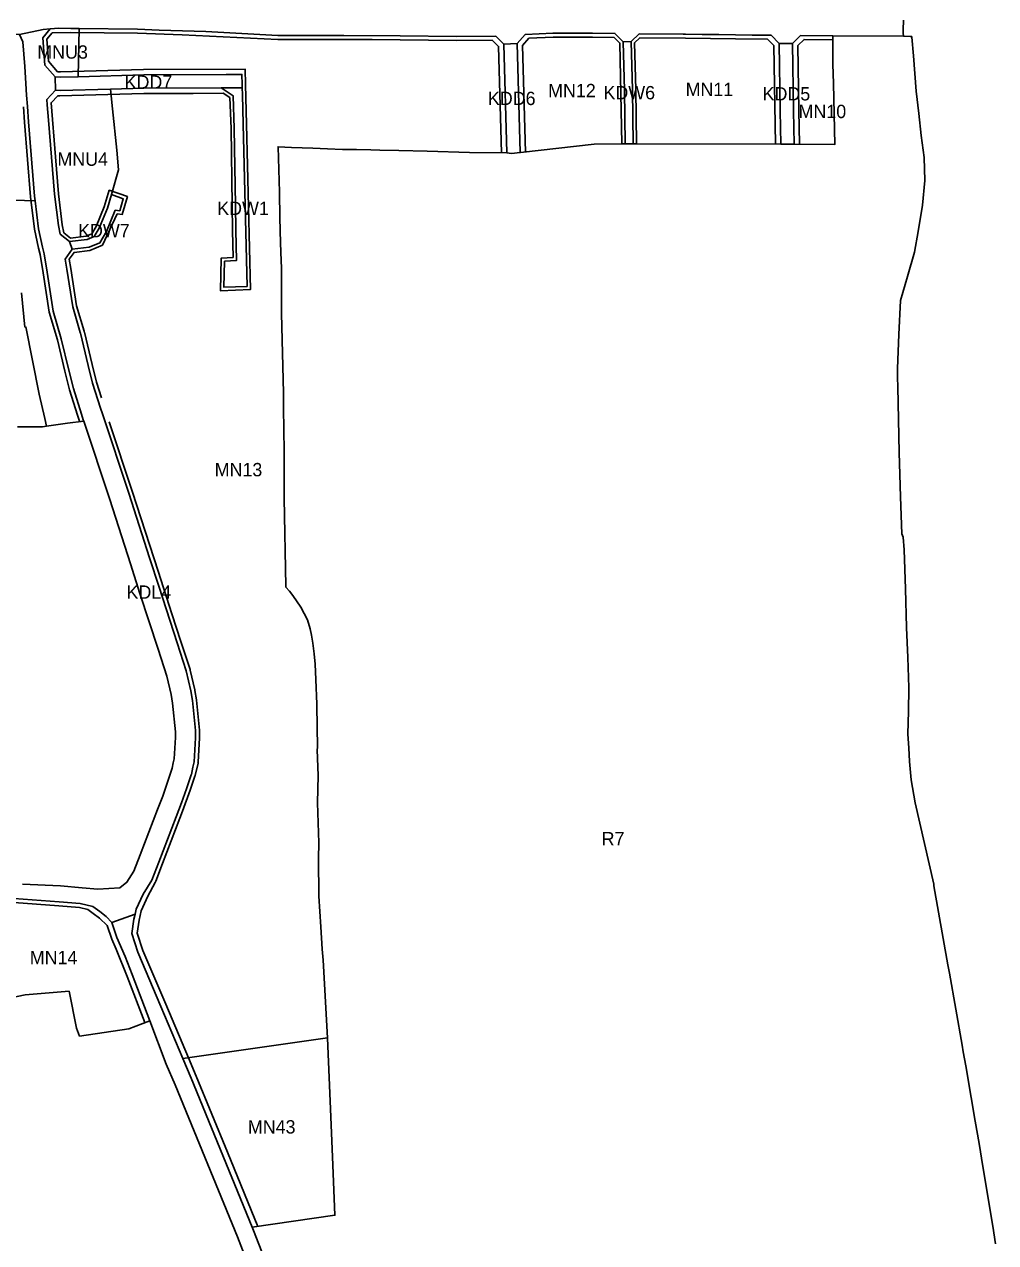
# Model space of a CAD drawing. Extents: x 7440055 to 7442242, y 5549003 to 5552256.
# Drawn here: x 7441503 to 7442231, y 5550566 to 5551479 of the extents above; entities that cross this region are included whole.
import ezdxf

# ---------------------------------------------------------------- set-up
doc = ezdxf.new("R2010")
doc.units = 0
for name, color, linetype in [('linie_rozgraniczajace', 7, 'Continuous'), ('linie_zabudowy_nieprzekraczalne', 7, 'Continuous'), ('oznaczenia_przeznaczen', 7, 'Continuous')]:
    doc.layers.add(name, color=color, linetype=linetype)

msp = doc.modelspace()

# ---------------------------------------------------------------- linework, layer by layer
at = {"layer": 'linie_rozgraniczajace'}
for points in [[(7441693.25, 5551470.85), (7441639.3, 5551473.7), (7441604.38, 5551474.86), (7441588.23, 5551475.46), (7441544.55, 5551475.94), (7441538.35, 5551476.01), (7441529.3, 5551476.2), (7441522.84, 5551475.74), (7441517.61, 5551475.36), (7441499.81, 5551471.5)], [(7441499.81, 5551471.5), (7441517.61, 5551475.36), (7441522.84, 5551475.74), (7441517.28, 5551469.14), (7441518.71, 5551448.66), (7441526.46, 5551439.82), (7441526.82, 5551429.77), (7441520.27, 5551422.86), (7441520.62, 5551418.73), (7441521.52, 5551407.33), (7441526, 5551351.81), (7441528.88, 5551328.46), (7441530.21, 5551322.02), (7441537.3, 5551316.36), (7441539.22, 5551310.56), (7441534.07, 5551303.06), (7441535.21, 5551295.75), (7441539.62, 5551267.5), (7441545.32, 5551248.19), (7441545.45, 5551247.82)], [(7441534.07, 5551303.06), (7441539.22, 5551310.56), (7441551.9, 5551312.17), (7441560.01, 5551315.49), (7441564.89, 5551323.79), (7441571.57, 5551339.78), (7441574.89, 5551339.45), (7441577.56, 5551348.48), (7441568.65, 5551351.57), (7441574.05, 5551370.21), (7441572.58, 5551384.86), (7441569.45, 5551415.93), (7441567.98, 5551430.58), (7441592.96, 5551431.25), (7441650.76, 5551431.56), (7441659.81, 5551425.63), (7441660.71, 5551401.1), (7441661.13, 5551372.41), (7441661.54, 5551343.71), (7441661.9, 5551324.82), (7441662.32, 5551302.13), (7441653.35, 5551301.58), (7441652.87, 5551282.1), (7441670.23, 5551282.8), (7441667.42, 5551404.41), (7441666.79, 5551426.65), (7441666.65, 5551431.65), (7441666.58, 5551434.03), (7441666.34, 5551441.65), (7441654.71, 5551441.59), (7441592.8, 5551441.25), (7441543.81, 5551439.93), (7441544.55, 5551475.94), (7441588.23, 5551475.46), (7441604.38, 5551474.86), (7441639.3, 5551473.7), (7441693.25, 5551470.85), (7441742.78, 5551470.89), (7441785.02, 5551470.51), (7441827.26, 5551470.12), (7441856.51, 5551470.3), (7441862.59, 5551464.42), (7441864.83, 5551382.91), (7441836.8, 5551383.23), (7441805.25, 5551384.05), (7441784.06, 5551384.63), (7441769.64, 5551384.95), (7441762.88, 5551385.07), (7441752.28, 5551385.26), (7441741.69, 5551385.44), (7441730.55, 5551385.89), (7441719.41, 5551386.33), (7441703.43, 5551386.97), (7441693.43, 5551387.37), (7441694.46, 5551353.42), (7441694.77, 5551334.17), (7441695.36, 5551315.46), (7441695.79, 5551301.84), (7441695.95, 5551296.75), (7441696.11, 5551262.51), (7441696.89, 5551232.75), (7441697.66, 5551202.99), (7441697.57, 5551192.59), (7441697.82, 5551174.47), (7441698.01, 5551160.09), (7441698.03, 5551124.12), (7441699.32, 5551057.97), (7441699.39, 5551057.36), (7441701.93, 5551054.22), (7441704.48, 5551051.08), (7441710.5, 5551042.42), (7441715.49, 5551032.76), (7441717.49, 5551026.12), (7441718.43, 5551021.35), (7441719.64, 5551015.27), (7441720.51, 5551007.47), (7441721.38, 5550999.68), (7441721.55, 5550993.9), (7441721.71, 5550988.12), (7441722.43, 5550969.68), (7441722.47, 5550968.55), (7441722.68, 5550952.91), (7441722.9, 5550937.27), (7441722.64, 5550935.46), (7441723.39, 5550916.2), (7441722.91, 5550895.73), (7441723.91, 5550865.75), (7441723.79, 5550853.91), (7441724.13, 5550825.71), (7441725.56, 5550802.81), (7441726.41, 5550786.1), (7441727.28, 5550777.68), (7441730.56, 5550719.57), (7441622.21, 5550704.09), (7441605.6, 5550743.12), (7441588.43, 5550783.71), (7441583.94, 5550797.64), (7441585.54, 5550808.42), (7441586.36, 5550812.21), (7441587.17, 5550816)], [(7442161.87, 5551482.19), (7442161.78, 5551475), (7442161.83, 5551472.6), (7442161.89, 5551470.19), (7442108.98, 5551470.62), (7442084.85, 5551470.85), (7442078.87, 5551464.91), (7442068.87, 5551464.87), (7442062.85, 5551470.95), (7442048.64, 5551471.13), (7442023.64, 5551471.44), (7442011.14, 5551471.6), (7441998.64, 5551471.75), (7441996.94, 5551471.77), (7441964.04, 5551472.18), (7441958.01, 5551466.29), (7441952.03, 5551466.19), (7441945.74, 5551472.41), (7441929.05, 5551472.61), (7441899.38, 5551472.48), (7441878.87, 5551471.68), (7441878.6, 5551471.65), (7441872.58, 5551464.86), (7441862.59, 5551464.42), (7441856.51, 5551470.3), (7441827.26, 5551470.12), (7441785.02, 5551470.51), (7441742.78, 5551470.89), (7441693.25, 5551470.85)], [(7441501.97, 5550834.71), (7441530.39, 5550833.54), (7441546.72, 5550832.06), (7441558.57, 5550831.01), (7441574.99, 5550831.99), (7441580.21, 5550836.2), (7441585.46, 5550844.47), (7441590.06, 5550856.66), (7441603.14, 5550890.64), (7441607.04, 5550900.78), (7441614.18, 5550921.62), (7441615.01, 5550925.7), (7441615.76, 5550928.67), (7441616.72, 5550944.58), (7441616.58, 5550948.85), (7441614.43, 5550970.45), (7441613.47, 5550976.83), (7441610.26, 5550990.64), (7441603.61, 5551010.92), (7441590.03, 5551052.68), (7441582.88, 5551074.83), (7441567.41, 5551123.04), (7441547.86, 5551181.86), (7441547.59, 5551182.67), (7441546.2, 5551187.08), (7441540.15, 5551206.18), (7441536.68, 5551220.02), (7441531.04, 5551243.58), (7441524.95, 5551264.21), (7441520.39, 5551293.43), (7441518.24, 5551307.26), (7441516.93, 5551312.11), (7441514.07, 5551326.03), (7441511.48, 5551346.99), (7441511.08, 5551350.28), (7441506.57, 5551406.14), (7441505.67, 5551417.51), (7441504.95, 5551426.05), (7441504.59, 5551434.9), (7441503.74, 5551447.63), (7441502.36, 5551466.11)], [(7441691.57, 5550533), (7441675.15, 5550575.24), (7441674.17, 5550577.63), (7441736.11, 5550586.61), (7441734.26, 5550630.28), (7441732.48, 5550672.04), (7441730.58, 5550719.25), (7441730.56, 5550719.57), (7441727.28, 5550777.68), (7441726.41, 5550786.1), (7441725.56, 5550802.81), (7441724.13, 5550825.71), (7441723.79, 5550853.91), (7441723.91, 5550865.75), (7441722.91, 5550895.73), (7441723.39, 5550916.2), (7441722.64, 5550935.46), (7441722.9, 5550937.27), (7441722.68, 5550952.91), (7441722.47, 5550968.55), (7441722.43, 5550969.68), (7441721.71, 5550988.12), (7441721.55, 5550993.9), (7441721.38, 5550999.68), (7441720.51, 5551007.47), (7441719.64, 5551015.27), (7441718.43, 5551021.35), (7441717.49, 5551026.12), (7441715.49, 5551032.76), (7441710.5, 5551042.42), (7441704.48, 5551051.08), (7441701.93, 5551054.22), (7441699.39, 5551057.36), (7441699.32, 5551057.97), (7441698.03, 5551124.12), (7441698.01, 5551160.09), (7441697.82, 5551174.47), (7441697.57, 5551192.59), (7441697.66, 5551202.99), (7441696.89, 5551232.75), (7441696.11, 5551262.51), (7441695.95, 5551296.75), (7441695.79, 5551301.84), (7441695.36, 5551315.46), (7441694.77, 5551334.17), (7441694.46, 5551353.42), (7441693.43, 5551387.37), (7441703.43, 5551386.97), (7441719.41, 5551386.33), (7441730.55, 5551385.89), (7441741.69, 5551385.44), (7441752.28, 5551385.26), (7441762.88, 5551385.07), (7441769.64, 5551384.95), (7441784.06, 5551384.63), (7441805.25, 5551384.05), (7441836.8, 5551383.23), (7441864.83, 5551382.91), (7441868.35, 5551382.42), (7441874.83, 5551383.13), (7441875.05, 5551383.16), (7441930.22, 5551389.27), (7441951.35, 5551389.61), (7441953.38, 5551389.64), (7441954.39, 5551389.66), (7441958.42, 5551389.72), (7441959.36, 5551389.72), (7441961.34, 5551389.73), (7442070.09, 5551389.35), (7442080.09, 5551389.34), (7442110.64, 5551389.24), (7442109.43, 5551434.74), (7442109.16, 5551449.29), (7442108.98, 5551470.62), (7442161.89, 5551470.19), (7442167.01, 5551470.05), (7442168.21, 5551470.02), (7442168.12, 5551469.49), (7442169.51, 5551455.64), (7442171.49, 5551429.02), (7442173.4, 5551412.46), (7442175.3, 5551395.9), (7442177.42, 5551379.39), (7442178.05, 5551362.03), (7442176.32, 5551343.77), (7442172.94, 5551323.86), (7442170.33, 5551308.42), (7442164.97, 5551290.28), (7442159.61, 5551272.14), (7442158.5, 5551246.73), (7442157.4, 5551221.33), (7442157.53, 5551214.43)], [(7441503.41, 5551347.09), (7441511.48, 5551346.99), (7441514.07, 5551326.03), (7441516.93, 5551312.11), (7441518.24, 5551307.26), (7441520.39, 5551293.43), (7441524.95, 5551264.21), (7441531.04, 5551243.58), (7441536.68, 5551220.02), (7441540.15, 5551206.18), (7441546.2, 5551187.08), (7441547.59, 5551182.67), (7441547.86, 5551181.86), (7441535.8, 5551180.17), (7441519.97, 5551177.95), (7441518.65, 5551183.66), (7441514.44, 5551201.95), (7441509.51, 5551227.17), (7441504.57, 5551252.38), (7441503.83, 5551252.33), (7441501.34, 5551277.98)], [(7441587.17, 5550816), (7441592.32, 5550827.29), (7441598.95, 5550837.73), (7441604.07, 5550851.32), (7441617.14, 5550885.25), (7441621.14, 5550895.65), (7441624.76, 5550906.22), (7441628.38, 5550916.79), (7441628.55, 5550917.03), (7441629.63, 5550922.36), (7441630.65, 5550926.35), (7441631.74, 5550944.38), (7441631.55, 5550949.85), (7441629.32, 5550972.3), (7441628.22, 5550979.64), (7441624.72, 5550994.68), (7441617.86, 5551015.58), (7441604.3, 5551057.3), (7441597.16, 5551079.43), (7441581.67, 5551127.69), (7441561.86, 5551187.3), (7441560.49, 5551191.61), (7441554.59, 5551210.27), (7441551.25, 5551223.59), (7441545.45, 5551247.82), (7441545.32, 5551248.19), (7441539.62, 5551267.5), (7441535.21, 5551295.75), (7441534.07, 5551303.06)], [(7441501.34, 5551277.98), (7441503.83, 5551252.33), (7441504.57, 5551252.38), (7441509.51, 5551227.17), (7441514.44, 5551201.95), (7441518.65, 5551183.66), (7441519.97, 5551177.95), (7441517.12, 5551177.56), (7441498.21, 5551177.47)], [(7441545.45, 5551247.82), (7441551.25, 5551223.59), (7441554.59, 5551210.27), (7441560.49, 5551191.61), (7441561.86, 5551187.3), (7441581.67, 5551127.69), (7441597.16, 5551079.43), (7441604.3, 5551057.3), (7441617.86, 5551015.58), (7441624.72, 5550994.68), (7441628.22, 5550979.64), (7441629.32, 5550972.3), (7441631.55, 5550949.85), (7441631.74, 5550944.38), (7441630.65, 5550926.35), (7441629.63, 5550922.36), (7441628.55, 5550917.03), (7441628.38, 5550916.79), (7441624.76, 5550906.22), (7441621.14, 5550895.65), (7441617.14, 5550885.25), (7441604.07, 5550851.32), (7441598.95, 5550837.73), (7441592.32, 5550827.29), (7441587.17, 5550816), (7441586.36, 5550812.21), (7441569.04, 5550806.07), (7441564.63, 5550810.61), (7441559.99, 5550814.21), (7441554.71, 5550817.95), (7441545.23, 5550820.15), (7441529.41, 5550821.58), (7441495.87, 5550823.99)], [(7442157.53, 5551214.43), (7442157.67, 5551207.53), (7442158.15, 5551182.9), (7442158.63, 5551158.28), (7442159.17, 5551141.7), (7442159.71, 5551125.12), (7442160.63, 5551097.19), (7442161.79, 5551094.78), (7442162.57, 5551085.32), (7442163.44, 5551056.16), (7442164.3, 5551027), (7442165.18, 5551004.63), (7442166.06, 5550982.26), (7442166.07, 5550981.62), (7442165.7, 5550964.35), (7442165.32, 5550947.09), (7442165.86, 5550936.84), (7442166.4, 5550926.59), (7442167.69, 5550913.05), (7442170.59, 5550895.59), (7442184.58, 5550834.67), (7442184.77, 5550833.57), (7442195.25, 5550774.19), (7442196.33, 5550768.08), (7442205.89, 5550714), (7442206.74, 5550709.15), (7442208.6, 5550698.62), (7442212.63, 5550674.78), (7442215.67, 5550657.13), (7442218.56, 5550640.29), (7442221.52, 5550623.06), (7442228.82, 5550578.31), (7442230.98, 5550565.09)], [(7441498.21, 5551177.47), (7441517.12, 5551177.56), (7441519.97, 5551177.95), (7441535.8, 5551180.17), (7441547.86, 5551181.86), (7441567.41, 5551123.04), (7441582.88, 5551074.83), (7441590.03, 5551052.68), (7441603.61, 5551010.92), (7441610.26, 5550990.64), (7441613.47, 5550976.83), (7441614.43, 5550970.45), (7441616.58, 5550948.85), (7441616.72, 5550944.58), (7441615.76, 5550928.67), (7441615.01, 5550925.7), (7441614.18, 5550921.62), (7441607.04, 5550900.78), (7441603.14, 5550890.64), (7441590.06, 5550856.66), (7441585.46, 5550844.47), (7441580.21, 5550836.2), (7441574.99, 5550831.99), (7441558.57, 5550831.01), (7441546.72, 5550832.06), (7441530.39, 5550833.54), (7441501.97, 5550834.71)], [(7441495.87, 5550823.99), (7441529.41, 5550821.58), (7441545.23, 5550820.15), (7441554.71, 5550817.95), (7441559.99, 5550814.21), (7441564.63, 5550810.61), (7441569.04, 5550806.07), (7441572.79, 5550794.83), (7441578.94, 5550780.47), (7441584.17, 5550767.08), (7441597.33, 5550732.36), (7441581.68, 5550726.2), (7441544.8, 5550720.86), (7441542.52, 5550726.71), (7441536.97, 5550754.48), (7441504.13, 5550751.79), (7441478.71, 5550746.62)], [(7441569.04, 5550806.07), (7441586.36, 5550812.21), (7441585.54, 5550808.42), (7441583.94, 5550797.64), (7441588.43, 5550783.71), (7441605.6, 5550743.12), (7441622.21, 5550704.09), (7441628.5, 5550689.31), (7441674.17, 5550577.63), (7441675.15, 5550575.24), (7441691.57, 5550533)], [(7441699.94, 5550232.15), (7441687.08, 5550244.43), (7441676.3, 5550258.66), (7441669.51, 5550272.27), (7441664.38, 5550288.43), (7441662.51, 5550299.83), (7441661.39, 5550307.27), (7441661.19, 5550317.23), (7441661.63, 5550322.42), (7441670.89, 5550364.3), (7441674.11, 5550391.57), (7441678.34, 5550438.21), (7441680.84, 5550485.01), (7441681.55, 5550504.54), (7441682.13, 5550517.19), (7441679.16, 5550529.05), (7441663.07, 5550570.43), (7441616.45, 5550684.43), (7441609.63, 5550699.87), (7441597.33, 5550732.36), (7441584.17, 5550767.08), (7441578.94, 5550780.47), (7441572.79, 5550794.83), (7441569.04, 5550806.07)], [(7441478.71, 5550746.62), (7441504.13, 5550751.79), (7441536.97, 5550754.48), (7441542.52, 5550726.71), (7441544.8, 5550720.86), (7441581.68, 5550726.2), (7441597.33, 5550732.36), (7441609.63, 5550699.87), (7441616.45, 5550684.43), (7441663.07, 5550570.43), (7441679.16, 5550529.05)]]:
    msp.add_lwpolyline(points, dxfattribs=at)
for points in [[(7441517.28, 5551469.14), (7441522.84, 5551475.74), (7441529.3, 5551476.2), (7441538.35, 5551476.01), (7441544.55, 5551475.94), (7441543.81, 5551439.93), (7441530.35, 5551439.57), (7441526.46, 5551439.82), (7441518.71, 5551448.66)], [(7441458.47, 5551348.32), (7441458.67, 5551384.69), (7441458.88, 5551421.05), (7441459.01, 5551445.55), (7441459.15, 5551470.04), (7441459.78, 5551472.46), (7441499.81, 5551471.5), (7441502.36, 5551466.11), (7441503.74, 5551447.63), (7441504.59, 5551434.9), (7441504.95, 5551426.05), (7441505.67, 5551417.51), (7441506.57, 5551406.14), (7441511.08, 5551350.28), (7441511.48, 5551346.99), (7441503.41, 5551347.09)], [(7441864.83, 5551382.91), (7441862.59, 5551464.42), (7441872.58, 5551464.86), (7441874.83, 5551383.13), (7441868.35, 5551382.42)], [(7441874.83, 5551383.13), (7441872.58, 5551464.86), (7441878.6, 5551471.65), (7441878.87, 5551471.68), (7441899.38, 5551472.48), (7441929.05, 5551472.61), (7441945.74, 5551472.41), (7441952.03, 5551466.19), (7441952.99, 5551429.84), (7441953.38, 5551389.64), (7441951.35, 5551389.61), (7441930.22, 5551389.27), (7441875.05, 5551383.16)], [(7441953.38, 5551389.64), (7441952.99, 5551429.84), (7441952.03, 5551466.19), (7441958.01, 5551466.29), (7441958.95, 5551430.21), (7441959.36, 5551389.72), (7441958.42, 5551389.72), (7441954.39, 5551389.66)], [(7441959.36, 5551389.72), (7441958.95, 5551430.21), (7441958.01, 5551466.29), (7441964.04, 5551472.18), (7441996.94, 5551471.77), (7441998.64, 5551471.75), (7442011.14, 5551471.6), (7442023.64, 5551471.44), (7442048.64, 5551471.13), (7442062.85, 5551470.95), (7442068.87, 5551464.87), (7442069.68, 5551414.27), (7442070.09, 5551389.35), (7441961.34, 5551389.73)], [(7442070.09, 5551389.35), (7442069.68, 5551414.27), (7442068.87, 5551464.87), (7442078.87, 5551464.91), (7442079.68, 5551414.44), (7442080.09, 5551389.34)], [(7442080.09, 5551389.34), (7442079.68, 5551414.44), (7442078.87, 5551464.91), (7442084.85, 5551470.85), (7442108.98, 5551470.62), (7442109.16, 5551449.29), (7442109.43, 5551434.74), (7442110.64, 5551389.24)], [(7441526.82, 5551429.77), (7441526.46, 5551439.82), (7441530.35, 5551439.57), (7441543.81, 5551439.93), (7441592.8, 5551441.25), (7441654.71, 5551441.59), (7441666.34, 5551441.65), (7441666.58, 5551434.03), (7441666.65, 5551431.65), (7441650.76, 5551431.56), (7441592.96, 5551431.25), (7441567.98, 5551430.58), (7441530.17, 5551429.56)], [(7441520.27, 5551422.86), (7441526.82, 5551429.77), (7441530.17, 5551429.56), (7441567.98, 5551430.58), (7441569.45, 5551415.93), (7441572.58, 5551384.86), (7441574.05, 5551370.21), (7441568.65, 5551351.57), (7441565.69, 5551341.52), (7441559.52, 5551326.51), (7441555.6, 5551320.08), (7441550.4, 5551318.03), (7441537.3, 5551316.36), (7441530.21, 5551322.02), (7441528.88, 5551328.46), (7441526, 5551351.81), (7441521.52, 5551407.33), (7441520.62, 5551418.73)], [(7441652.87, 5551282.1), (7441653.35, 5551301.58), (7441662.32, 5551302.13), (7441661.9, 5551324.82), (7441661.54, 5551343.71), (7441661.13, 5551372.41), (7441660.71, 5551401.1), (7441659.81, 5551425.63), (7441650.76, 5551431.56), (7441666.65, 5551431.65), (7441666.79, 5551426.65), (7441667.42, 5551404.41), (7441670.23, 5551282.8)], [(7441537.3, 5551316.36), (7441550.4, 5551318.03), (7441555.6, 5551320.08), (7441559.52, 5551326.51), (7441565.69, 5551341.52), (7441568.65, 5551351.57), (7441577.56, 5551348.48), (7441574.89, 5551339.45), (7441571.57, 5551339.78), (7441564.89, 5551323.79), (7441560.01, 5551315.49), (7441551.9, 5551312.17), (7441539.22, 5551310.56)], [(7441622.21, 5550704.09), (7441730.56, 5550719.57), (7441730.58, 5550719.25), (7441732.48, 5550672.04), (7441734.26, 5550630.28), (7441736.11, 5550586.61), (7441674.17, 5550577.63), (7441628.5, 5550689.31)]]:
    msp.add_lwpolyline(points, close=True, dxfattribs=at)
at = {"layer": 'linie_zabudowy_nieprzekraczalne'}
for p, q in [((7441632.31, 5550972.52), (7441632.27, 5550972.82)), ((7441621.92, 5550889.34), (7441621.98, 5550889.48))]:
    msp.add_line(p, q, dxfattribs=at)
for points in [[(7441548.23, 5551248.96), (7441548.18, 5551249.12), (7441542.55, 5551268.16), (7441538.18, 5551296.21), (7441537.11, 5551303.07), (7441540.64, 5551308.22), (7441552.54, 5551309.74), (7441561.85, 5551313.55), (7441573.07, 5551337.12), (7441576.7, 5551336.76), (7441580.63, 5551350.07), (7441567, 5551354.79), (7441563.33, 5551342.35), (7441557.28, 5551327.64), (7441553.9, 5551322.1), (7441549.77, 5551320.47), (7441538.03, 5551318.97), (7441533.08, 5551322.92), (7441531.85, 5551328.94), (7441528.99, 5551352.11), (7441526.75, 5551379.81), (7441523.47, 5551420.43), (7441528.44, 5551425.66), (7441530.1, 5551425.56), (7441593.03, 5551427.25), (7441629.82, 5551427.45), (7441652.38, 5551427.51), (7441657.36, 5551424.25), (7441658.22, 5551401.04), (7441659.04, 5551343.67), (7441659.4, 5551324.78), (7441659.77, 5551304.48), (7441650.91, 5551303.93), (7441650.3, 5551279.49), (7441672.79, 5551280.41), (7441669.91, 5551404.48), (7441669.08, 5551434.11), (7441668.71, 5551445.66), (7441592.73, 5551445.25), (7441530.42, 5551443.57), (7441528.37, 5551443.7), (7441521.52, 5551451.53), (7441520.36, 5551468.13), (7441524.28, 5551472.79), (7441538.35, 5551473.01), (7441588.16, 5551472.46), (7441621.72, 5551471.28), (7441693.18, 5551467.85), (7441718.01, 5551467.87), (7441763.88, 5551467.7), (7441827.25, 5551467.13), (7441853.88, 5551467.28), (7441858.64, 5551462.68), (7441860.83, 5551382.8)], [(7441950.88, 5551389.6), (7441949.55, 5551465.13), (7441945.22, 5551469.41), (7441929.04, 5551469.61), (7441899.44, 5551469.48), (7441881.4, 5551468.78), (7441876.63, 5551463.39), (7441878.82, 5551383.41)], [(7442066.09, 5551389.28), (7442064.9, 5551463.2), (7442060.16, 5551467.99), (7442036.1, 5551468.28), (7441998.6, 5551468.75), (7441964.54, 5551469.18), (7441960.53, 5551465.26), (7441961.45, 5551430.26), (7441961.86, 5551389.7)], [(7442084.09, 5551389.4), (7442083.68, 5551414.5), (7442082.9, 5551463.27), (7442087.48, 5551467.82), (7442108.95, 5551467.62)], [(7441502.68, 5551417.27), (7441503.58, 5551405.9), (7441508.09, 5551349.98), (7441511.11, 5551325.54), (7441514.01, 5551311.42), (7441515.3, 5551306.64), (7441517.43, 5551292.97), (7441522.02, 5551263.55), (7441528.14, 5551242.81), (7441533.76, 5551219.31), (7441537.26, 5551205.36), (7441543.34, 5551186.18), (7441544.74, 5551181.75), (7441544.84, 5551181.44)], [(7441561.2, 5551199.31), (7441557.47, 5551211.09), (7441554.16, 5551224.31), (7441548.4, 5551248.37)], [(7441584.51, 5551128.65), (7441567.01, 5551181.32)], [(7441627.53, 5550995.74), (7441620.72, 5551016.51), (7441613.93, 5551037.37), (7441603.58, 5551069.29), (7441584.53, 5551128.6)], [(7441631.11, 5550980.44), (7441627.67, 5550995.23)], [(7441632.27, 5550972.82), (7441631.2, 5550979.97)], [(7441634.52, 5550950.24), (7441632.31, 5550972.52)], [(7441633.66, 5550926.43), (7441634.72, 5550944.06)], [(7441634.73, 5550944.63), (7441634.55, 5550949.85)], [(7441631.33, 5550916.24), (7441633.5, 5550925.41)], [(7441627.6, 5550905.27), (7441631.17, 5550915.68)], [(7441621.98, 5550889.48), (7441627.58, 5550905.2)], [(7441601.86, 5550836.96), (7441606.88, 5550850.25), (7441619.94, 5550884.18), (7441621.92, 5550889.34)], [(7441678.25, 5550578.22), (7441655.53, 5550633.79), (7441632.19, 5550690.85), (7441626.31, 5550704.66), (7441609.28, 5550744.69), (7441609.28, 5550744.68), (7441592.18, 5550785.1), (7441588.03, 5550797.98), (7441589.48, 5550807.7), (7441590.99, 5550814.73), (7441595.96, 5550825.63), (7441601.32, 5550835.87)], [(7441593.58, 5550730.95), (7441580.45, 5550765.62), (7441572.17, 5550786.11), (7441569.05, 5550793.41), (7441565.57, 5550803.84), (7441559.74, 5550809.34), (7441555, 5550812.84), (7441550.89, 5550815.76), (7441544.76, 5550817.18), (7441529.17, 5550818.59), (7441495.84, 5550820.99)]]:
    msp.add_lwpolyline(points, dxfattribs=at)
for centre, radius, start, end in [((7441541, 5551246.56), 7.62, 13.76353, 18.38362), ((7441584.34, 5551128.55), 0.19, 13.67131, 29.93151), ((7441602.14, 5550988.5), 26.41, 14.77638, 15.92389), ((7441624.08, 5550978.85), 7.21, 8.93782, 12.74279), ((7441630.4, 5550949.73), 4.16, 1.7009, 7.09651), ((7441626.75, 5550944.49), 7.99, 356.94951, 1.04032), ((7441627.41, 5550926.89), 6.26, 346.35709, 355.81306), ((7441627.02, 5550917.17), 4.41, 340.27196, 347.83725), ((7441627.13, 5550905.37), 0.475, 339.6559, 348.45331), ((7441596.66, 5550838.86), 5.53, 327.33269, 339.9585)]:
    msp.add_arc(centre, radius, start, end, dxfattribs=at)

# ---------------------------------------------------------------- texts
at = {"layer": 'oznaczenia_przeznaczen'}
for s, p in [('MNU3', (7441513.12, 5551453.45)), ('KDD7', (7441578.53, 5551430.94)), ('KDD6', (7441850.68, 5551418.69)), ('MN12', (7441895.78, 5551424.55)), ('KDW6', (7441937.23, 5551422.96)), ('MN11', (7441998.77, 5551425.41)), ('KDD5', (7442056.45, 5551422.12)), ('MN10', (7442083.37, 5551408.9)), ('MNU4', (7441528.2, 5551373.13)), ('KDW1', (7441647.91, 5551336.27)), ('KDW7', (7441543.68, 5551319.5)), ('MN13', (7441646, 5551140.43)), ('KDL4', (7441579.99, 5551048.64)), ('R7', (7441935.87, 5550863.81)), ('MN14', (7441507.48, 5550774.74)), ('MN43', (7441670.87, 5550647.85))]:
    msp.add_text(s, height=10, dxfattribs=at).set_placement(p)

doc.saveas('drawing.dxf')
